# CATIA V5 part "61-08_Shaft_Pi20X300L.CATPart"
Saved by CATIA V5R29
Part number: 61-08_Shaft_Pi20X150L
Bounding box of the stored display mesh (mm): x -10 to 10, y -10 to 10, z 0 to 150
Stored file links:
  C:\Users\Administrator\Desktop\10-14 작업\stopper\61-08_Shaft_Pi20X300L.CATPart
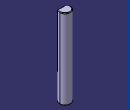
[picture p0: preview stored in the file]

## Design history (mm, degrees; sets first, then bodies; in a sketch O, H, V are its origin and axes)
Body1 (main body)
  Sketch1 on xy-plane, origin (0, 0, 0), H (1, 0, 0), V (0, 1, 0)
    circle A1 centre (0, 0) radius 10
    radius A1 = 10
  Pad1: profile Sketch1, direction (0, 0, 1), length 150
  Chamfer1: length 1, angle 45, on face of Pad1 from Sketch1.A1
  Sketch2 on end face of Pad1, origin (0, 0, 150), H (1, 0, 0), V (0, 1, 0)
    point P1 (0, -10)
    line L1 (10, -5) -> (10, -15)
    line L2 (10, -15) -> (-10, -15)
    line L3 (-10, -15) -> (-10, -5)
    line L4 (-10, -5) -> (10, -5)
    length L4 = 20
    distance L4 H = 5
    length L3 = 10
    coincidence: P1 V
    vertical: L1 V, L3 V
    horizontal: L2 H, L4 H
    equidistance: L1 L3 P1, L2 L4 P1
  Pocket1: profile Sketch2, direction (0, 0, -1), length 100
  Sketch3 on face of Pocket1 from Sketch2.L4, origin (-1.7277, -5, 285.0176), H (1, 0, 0), V (0, 0, 1)
    point P1 (1.7277, -145.0176)
    reference projected line E1 (9.211, -135.0176) -> (-5.7556, -135.0176) from edge [end face of Pad1 | face of Pocket1 from Sketch2.L4]
    reference projected line E2 through (1.7277, 0) direction (0, 1) from axis of face of Pad1 from Sketch1.A1
    distance P1 E1 = 10
    coincidence: P1 E2
  Hole1: placed by Sketch3, at (0, -5, 140) direction (0, 1, 0), diameter 3.242, depth 12, V-bottom angle 120, threaded "M4", thread diameter 4, thread depth 10, pitch 0.7
  RectPattern1: of Hole1, direction 1 instances 3, spacing 40, along edge [face of Pocket1 from Sketch2.L4 | face of Pad1 from Sketch1.A1]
